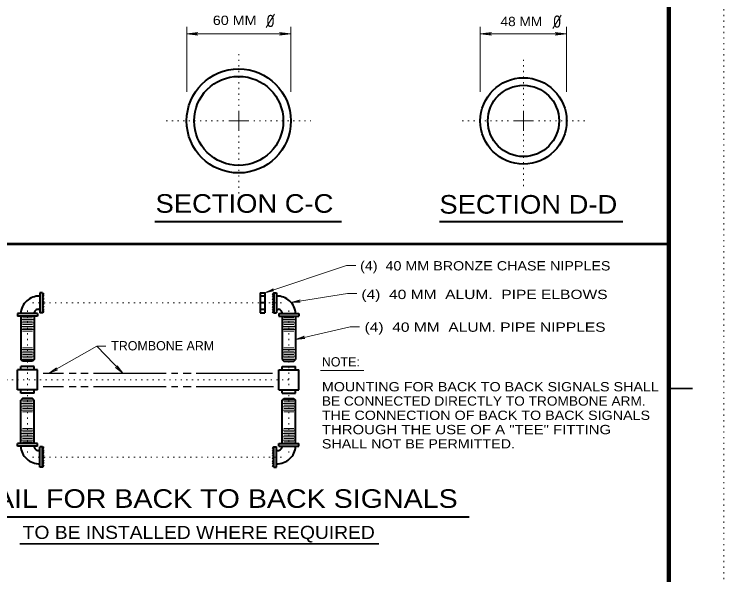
# Model space of a CAD drawing. Extents: x 312583 to 312854, y 144419 to 144597.
# Drawn here: x 312795.5 to 312853.5, y 144488.4 to 144534.2 of the extents above; entities that cross this region are included whole.
import ezdxf
from ezdxf.enums import TextEntityAlignment as Align

# ---------------------------------------------------------------- set-up
doc = ezdxf.new("R2010")
doc.units = 0
doc.header["$LTSCALE"] = 0.3
doc.linetypes.add('DOTTED', pattern=[1.5, 0.3, -1.2])
for name, color, linetype, lineweight in [('1', 7, 'Continuous', 35), ('2', 7, 'Continuous', 13), ('62', 7, 'DOTTED', 13)]:
    doc.layers.add(name, color=color, linetype=linetype, lineweight=lineweight)

msp = doc.modelspace()

# ---------------------------------------------------------------- linework, layer by layer
at = {"layer": '1', "lineweight": 158}
msp.add_line((312849, 144423.1446), (312849, 144585.0846), dxfattribs=at)
at = {"layer": '1', "lineweight": 53}
msp.add_line((312849, 144515.4129), (312762.6698, 144515.4129), dxfattribs=at)
at = {"layer": '1', "lineweight": 40}
for p, q in [((312797.6188, 144511.4311), (312797.6188, 144509.7904)), ((312797.8335, 144511.4311), (312797.6188, 144511.4311)), ((312797.8335, 144511.4311), (312797.8335, 144509.7904)), ((312797.8335, 144511.4311), (312797.9408, 144511.3314)), ((312815.6048, 144511.4311), (312815.9882, 144511.4311)), ((312815.6048, 144511.4311), (312815.6048, 144509.7904)), ((312815.9882, 144511.4311), (312815.9882, 144509.7904)), ((312816.7242, 144511.4311), (312816.6245, 144511.3314)), ((312816.7242, 144511.4311), (312816.7242, 144509.7904)), ((312816.7242, 144511.4311), (312816.9465, 144511.4311)), ((312816.9465, 144511.4311), (312816.9465, 144509.7904)), ((312797.8335, 144511.2241), (312797.9408, 144511.3314)), ((312797.8335, 144511.2241), (312797.9408, 144511.1244)), ((312797.8335, 144511.0171), (312797.9408, 144511.1244)), ((312797.8335, 144511.0171), (312797.9408, 144510.9174)), ((312797.8335, 144510.8101), (312797.9408, 144510.9174)), ((312797.8335, 144510.8101), (312797.9408, 144510.7028)), ((312815.9882, 144511.1628), (312815.6048, 144511.1628)), ((312816.7242, 144511.2241), (312816.6245, 144511.3314)), ((312816.7242, 144511.2241), (312816.6245, 144511.1244)), ((312816.7242, 144511.0171), (312816.6245, 144511.1244)), ((312816.7242, 144511.0171), (312816.6245, 144510.9174)), ((312816.7242, 144510.8101), (312816.6245, 144510.9174)), ((312816.7242, 144510.8101), (312816.6245, 144510.7028)), ((312797.8335, 144510.6031), (312797.9408, 144510.7028)), ((312797.8335, 144510.6031), (312797.9408, 144510.4958)), ((312797.8335, 144510.3961), (312797.9408, 144510.4958)), ((312797.8335, 144510.3961), (312797.9408, 144510.2888)), ((312797.8335, 144510.1891), (312797.9408, 144510.2888)), ((312815.9882, 144510.6108), (312815.6048, 144510.6108)), ((312816.7242, 144510.6031), (312816.6245, 144510.7028)), ((312816.7242, 144510.6031), (312816.6245, 144510.4958)), ((312816.7242, 144510.3961), (312816.6245, 144510.4958)), ((312816.7242, 144510.3961), (312816.6245, 144510.2888)), ((312816.7242, 144510.1891), (312816.6245, 144510.2888)), ((312795.7788, 144509.7368), (312795.7788, 144509.5144)), ((312797.4272, 144509.7368), (312795.7788, 144509.7368)), ((312797.4272, 144509.7368), (312797.4272, 144509.5144)), ((312797.6188, 144510.0818), (312797.5115, 144510.0818)), ((312797.8335, 144509.7904), (312797.6188, 144509.7904)), ((312797.8335, 144510.1891), (312797.9408, 144510.0818)), ((312797.8335, 144509.9744), (312797.9408, 144510.0818)), ((312797.8335, 144509.9744), (312797.9408, 144509.8748)), ((312797.8335, 144509.7904), (312797.9408, 144509.8748)), ((312815.9882, 144510.0818), (312815.6048, 144510.0818)), ((312815.6048, 144509.7904), (312815.9882, 144509.7904)), ((312816.7242, 144510.1891), (312816.6245, 144510.0818)), ((312816.7242, 144509.9744), (312816.6245, 144510.0818)), ((312816.7242, 144509.9744), (312816.6245, 144509.8748)), ((312816.7242, 144509.7904), (312816.6245, 144509.8748)), ((312816.7242, 144509.7904), (312816.9465, 144509.7904)), ((312816.9465, 144510.0818), (312817.0462, 144510.0818)), ((312817.1382, 144509.7368), (312817.1382, 144509.5144)), ((312817.1382, 144509.7368), (312818.7788, 144509.7368)), ((312818.7788, 144509.7368), (312818.7788, 144509.5144)), ((312797.4272, 144509.5144), (312795.7788, 144509.5144)), ((312796.0548, 144509.5144), (312796.0548, 144505.9724)), ((312797.1512, 144509.5144), (312797.1512, 144505.9724)), ((312817.1382, 144509.5144), (312818.7788, 144509.5144)), ((312817.4142, 144509.5144), (312817.4142, 144505.9724)), ((312818.5105, 144509.5144), (312818.5105, 144505.9724)), ((312796.1928, 144505.8344), (312796.0548, 144505.9724)), ((312797.0132, 144505.8344), (312796.1928, 144505.8344)), ((312797.1512, 144505.9724), (312797.0132, 144505.8344)), ((312817.4142, 144505.9724), (312817.5522, 144505.8344)), ((312817.5522, 144505.8344), (312818.3725, 144505.8344)), ((312818.3725, 144505.8344), (312818.5105, 144505.9724)), ((312795.7788, 144503.4961), (312795.7788, 144505.1368)), ((312797.4272, 144505.1368), (312795.7788, 144505.1368)), ((312797.1512, 144505.4128), (312796.0548, 144505.4128)), ((312796.0548, 144505.1368), (312796.0548, 144505.4128)), ((312797.1512, 144505.1368), (312797.1512, 144505.4128)), ((312797.4272, 144503.4961), (312797.4272, 144505.1368)), ((312817.1382, 144503.4961), (312817.1382, 144505.1368)), ((312817.1382, 144505.1368), (312818.7788, 144505.1368)), ((312817.4142, 144505.4128), (312818.5105, 144505.4128)), ((312817.4142, 144505.1368), (312817.4142, 144505.4128)), ((312818.5105, 144505.1368), (312818.5105, 144505.4128)), ((312818.7788, 144503.4961), (312818.7788, 144505.1368)), ((312797.4272, 144503.4961), (312795.7788, 144503.4961)), ((312796.0548, 144503.2201), (312796.0548, 144503.4961)), ((312797.1512, 144503.2201), (312797.1512, 144503.4961)), ((312817.1382, 144503.4961), (312818.7788, 144503.4961)), ((312817.4142, 144503.2201), (312817.4142, 144503.4961)), ((312818.5105, 144503.2201), (312818.5105, 144503.4961)), ((312797.1512, 144503.2201), (312796.0548, 144503.2201)), ((312796.1928, 144502.7908), (312796.0548, 144502.6604)), ((312797.0132, 144502.7908), (312796.1928, 144502.7908)), ((312797.1512, 144502.6604), (312797.0132, 144502.7908)), ((312817.4142, 144503.2201), (312818.5105, 144503.2201)), ((312817.4142, 144502.6604), (312817.5522, 144502.7908)), ((312817.5522, 144502.7908), (312818.3725, 144502.7908)), ((312818.3725, 144502.7908), (312818.5105, 144502.6604)), ((312796.0548, 144499.1108), (312796.0548, 144502.6604)), ((312797.1512, 144499.1108), (312797.1512, 144502.6604)), ((312817.4142, 144499.1108), (312817.4142, 144502.6604)), ((312818.5105, 144499.1108), (312818.5105, 144502.6604)), ((312795.7788, 144498.8961), (312795.7788, 144499.1108)), ((312797.4272, 144499.1108), (312795.7788, 144499.1108)), ((312797.4272, 144498.8961), (312795.7788, 144498.8961)), ((312797.4272, 144498.8961), (312797.4272, 144499.1108)), ((312797.6188, 144497.1941), (312797.6188, 144498.8424)), ((312797.8335, 144498.8424), (312797.6188, 144498.8424)), ((312797.8335, 144497.1941), (312797.8335, 144498.8424)), ((312797.8335, 144498.8424), (312797.9408, 144498.7581)), ((312797.8335, 144498.6508), (312797.9408, 144498.7581)), ((312797.8335, 144498.6508), (312797.9408, 144498.5511)), ((312816.7242, 144498.8424), (312816.6245, 144498.7581)), ((312816.7242, 144498.6508), (312816.6245, 144498.7581)), ((312816.7242, 144498.6508), (312816.6245, 144498.5511)), ((312816.7242, 144497.1941), (312816.7242, 144498.8424)), ((312816.7242, 144498.8424), (312816.9465, 144498.8424)), ((312816.9465, 144497.1941), (312816.9465, 144498.8424)), ((312817.1382, 144498.8961), (312817.1382, 144499.1108)), ((312817.1382, 144499.1108), (312818.7788, 144499.1108)), ((312817.1382, 144498.8961), (312818.7788, 144498.8961)), ((312818.7788, 144498.8961), (312818.7788, 144499.1108)), ((312797.6188, 144498.5434), (312797.5115, 144498.5434)), ((312797.8335, 144498.4438), (312797.9408, 144498.5511)), ((312797.8335, 144498.4438), (312797.9408, 144498.3441)), ((312797.8335, 144498.2368), (312797.9408, 144498.3441)), ((312797.8335, 144498.2368), (312797.9408, 144498.1294)), ((312797.8335, 144498.0298), (312797.9408, 144498.1294)), ((312816.7242, 144498.4438), (312816.6245, 144498.5511)), ((312816.7242, 144498.4438), (312816.6245, 144498.3441)), ((312816.7242, 144498.2368), (312816.6245, 144498.3441)), ((312816.7242, 144498.2368), (312816.6245, 144498.1294)), ((312816.7242, 144498.0298), (312816.6245, 144498.1294)), ((312816.9465, 144498.5434), (312817.0462, 144498.5434)), ((312797.8335, 144498.0298), (312797.9408, 144497.9224)), ((312797.8335, 144497.8228), (312797.9408, 144497.9224)), ((312797.8335, 144497.8228), (312797.9408, 144497.7154)), ((312797.8335, 144497.6158), (312797.9408, 144497.7154)), ((312797.8335, 144497.6158), (312797.9408, 144497.5084)), ((312797.8335, 144497.4011), (312797.9408, 144497.5084)), ((312816.7242, 144498.0298), (312816.6245, 144497.9224)), ((312816.7242, 144497.8228), (312816.6245, 144497.9224)), ((312816.7242, 144497.8228), (312816.6245, 144497.7154)), ((312816.7242, 144497.6158), (312816.6245, 144497.7154)), ((312816.7242, 144497.6158), (312816.6245, 144497.5084)), ((312816.7242, 144497.4011), (312816.6245, 144497.5084)), ((312797.8335, 144497.1941), (312797.6188, 144497.1941)), ((312797.8335, 144497.4011), (312797.9408, 144497.3014)), ((312797.8335, 144497.1941), (312797.9408, 144497.3014)), ((312816.7242, 144497.4011), (312816.6245, 144497.3014)), ((312816.7242, 144497.1941), (312816.6245, 144497.3014)), ((312816.7242, 144497.1941), (312816.9465, 144497.1941))]:
    msp.add_line(p, q, dxfattribs=at)
at = {"layer": '1', "linetype": 'DOTTED', "lineweight": 13}
for p, q in [((312796.5992, 144498.3748), (312796.5992, 144510.2811)), ((312797.0132, 144510.6108), (312817.6365, 144510.6108)), ((312817.9585, 144498.3748), (312817.9585, 144510.2811)), ((312792.5588, 144504.3164), (312818.2038, 144504.3164)), ((312797.0132, 144498.0144), (312817.6365, 144498.0144))]:
    msp.add_line(p, q, dxfattribs=at)
at = {"layer": '1', "lineweight": 13}
for p, q in [((312797.1512, 144509.2461), (312796.0548, 144509.2461)), ((312797.0132, 144509.3841), (312796.1928, 144509.3841)), ((312797.0132, 144509.1081), (312796.1928, 144509.1081)), ((312817.4142, 144509.2461), (312818.5105, 144509.2461)), ((312817.5522, 144509.3841), (312818.3725, 144509.3841)), ((312817.5522, 144509.1081), (312818.3725, 144509.1081)), ((312797.1512, 144508.9701), (312796.0548, 144508.9701)), ((312797.1512, 144508.6941), (312796.0548, 144508.6941)), ((312797.0132, 144508.8321), (312796.1928, 144508.8321)), ((312797.0132, 144508.5561), (312796.1928, 144508.5561)), ((312817.4142, 144508.9701), (312818.5105, 144508.9701)), ((312817.4142, 144508.6941), (312818.5105, 144508.6941)), ((312817.5522, 144508.8321), (312818.3725, 144508.8321)), ((312817.5522, 144508.5561), (312818.3725, 144508.5561)), ((312797.1512, 144508.4258), (312796.0548, 144508.4258)), ((312797.0132, 144508.2878), (312796.1928, 144508.2878)), ((312817.4142, 144508.4258), (312818.5105, 144508.4258)), ((312817.5522, 144508.2878), (312818.3725, 144508.2878)), ((312797.1512, 144506.7928), (312796.0548, 144506.7928)), ((312797.0132, 144506.9308), (312796.1928, 144506.9308)), ((312817.4142, 144506.7928), (312818.5105, 144506.7928)), ((312817.5522, 144506.9308), (312818.3725, 144506.9308)), ((312797.1512, 144506.5244), (312796.0548, 144506.5244)), ((312797.1512, 144506.2484), (312796.0548, 144506.2484)), ((312797.0132, 144506.6548), (312796.1928, 144506.6548)), ((312797.0132, 144506.3864), (312796.1928, 144506.3864)), ((312817.4142, 144506.5244), (312818.5105, 144506.5244)), ((312817.4142, 144506.2484), (312818.5105, 144506.2484)), ((312817.5522, 144506.6548), (312818.3725, 144506.6548)), ((312817.5522, 144506.3864), (312818.3725, 144506.3864)), ((312797.1512, 144505.9724), (312796.0548, 144505.9724)), ((312797.0132, 144506.1104), (312796.1928, 144506.1104)), ((312817.4142, 144505.9724), (312818.5105, 144505.9724)), ((312817.5522, 144506.1104), (312818.3725, 144506.1104)), ((312797.1512, 144502.6604), (312796.0548, 144502.6604)), ((312797.1512, 144502.3844), (312796.0548, 144502.3844)), ((312797.1512, 144502.1084), (312796.0548, 144502.1084)), ((312797.0132, 144502.5224), (312796.1928, 144502.5224)), ((312797.0132, 144502.2464), (312796.1928, 144502.2464)), ((312817.4142, 144502.6604), (312818.5105, 144502.6604)), ((312817.4142, 144502.3844), (312818.5105, 144502.3844)), ((312817.4142, 144502.1084), (312818.5105, 144502.1084)), ((312817.5522, 144502.5224), (312818.3725, 144502.5224)), ((312817.5522, 144502.2464), (312818.3725, 144502.2464)), ((312797.1512, 144501.8324), (312796.0548, 144501.8324)), ((312797.0132, 144501.9704), (312796.1928, 144501.9704)), ((312797.0132, 144501.7021), (312796.1928, 144501.7021)), ((312817.4142, 144501.8324), (312818.5105, 144501.8324)), ((312817.5522, 144501.9704), (312818.3725, 144501.9704)), ((312817.5522, 144501.7021), (312818.3725, 144501.7021)), ((312797.1512, 144500.2071), (312796.0548, 144500.2071)), ((312797.1512, 144499.9311), (312796.0548, 144499.9311)), ((312797.0132, 144500.3451), (312796.1928, 144500.3451)), ((312797.0132, 144500.0691), (312796.1928, 144500.0691)), ((312797.0132, 144499.8008), (312796.1928, 144499.8008)), ((312817.4142, 144500.2071), (312818.5105, 144500.2071)), ((312817.4142, 144499.9311), (312818.5105, 144499.9311)), ((312817.5522, 144500.3451), (312818.3725, 144500.3451)), ((312817.5522, 144500.0691), (312818.3725, 144500.0691)), ((312817.5522, 144499.8008), (312818.3725, 144499.8008)), ((312797.1512, 144499.6628), (312796.0548, 144499.6628)), ((312797.1512, 144499.3868), (312796.0548, 144499.3868)), ((312797.0132, 144499.5248), (312796.1928, 144499.5248)), ((312797.0132, 144499.2488), (312796.1928, 144499.2488)), ((312817.4142, 144499.6628), (312818.5105, 144499.6628)), ((312817.4142, 144499.3868), (312818.5105, 144499.3868)), ((312817.5522, 144499.5248), (312818.3725, 144499.5248)), ((312817.5522, 144499.2488), (312818.3725, 144499.2488))]:
    msp.add_line(p, q, dxfattribs=at)
at = {"layer": '1', "lineweight": 25}
for p, q in [((312797.8718, 144504.8608), (312799.5508, 144504.8608)), ((312800.0185, 144504.8608), (312800.5782, 144504.8608)), ((312800.9538, 144504.8608), (312801.5672, 144504.8608)), ((312801.9888, 144504.8608), (312807.9458, 144504.8608)), ((312808.3675, 144504.8608), (312808.8812, 144504.8608)), ((312809.3105, 144504.8608), (312809.9622, 144504.8608)), ((312810.3838, 144504.8608), (312816.6245, 144504.8608)), ((312797.8718, 144503.7644), (312799.5508, 144503.7644)), ((312800.0185, 144503.7644), (312800.5782, 144503.7644)), ((312800.9538, 144503.7644), (312801.5672, 144503.7644)), ((312801.9888, 144503.7644), (312807.9458, 144503.7644)), ((312808.3675, 144503.7644), (312808.8812, 144503.7644)), ((312809.3105, 144503.7644), (312809.9622, 144503.7644)), ((312810.3838, 144503.7644), (312816.7012, 144503.7644))]:
    msp.add_line(p, q, dxfattribs=at)
at = {"layer": '1'}
msp.add_line((312849, 144503.6216), (312850.932, 144503.6216), dxfattribs=at)
at = {"layer": '1', "lineweight": 40}
for centre, radius in [((312813.8612, 144525.4808), 4.255), ((312813.8612, 144525.4808), 3.6417), ((312837.1297, 144525.4808), 3.5267), ((312837.1297, 144525.4808), 2.9133)]:
    msp.add_circle(centre, radius, dxfattribs=at)
for centre, radius, start, end in [((312797.5389, 144509.6778), 1.4853, 87.04189, 177.70529), ((312817.0231, 144509.6778), 1.4853, 2.29471, 92.95811), ((312797.5049, 144509.7299), 0.3549, 88.7647, 178.79588), ((312817.0571, 144509.7299), 0.3549, 1.20412, 91.2353), ((312797.5389, 144498.9539), 1.4853, 182.29471, 272.95811), ((312797.5049, 144498.9019), 0.3549, 181.20412, 271.2353), ((312817.0231, 144498.9539), 1.4853, 267.04189, 357.70529), ((312817.0571, 144498.9019), 0.3549, 268.7647, 358.79588)]:
    msp.add_arc(centre, radius, start, end, dxfattribs=at)
at = {"layer": '2'}
for p, q in [((312816.1029, 144533.1076), (312816.7776, 144534.1963)), ((312839.5309, 144533.0463), (312840.2056, 144534.1349)), ((312809.6093, 144527.8636), (312809.6093, 144533.1843)), ((312818.1193, 144527.8636), (312818.1193, 144533.1843)), ((312833.6046, 144527.8636), (312833.6046, 144533.1843)), ((312840.6579, 144527.8636), (312840.6579, 144533.1843)), ((312809.6093, 144532.6016), (312810.5293, 144532.7166)), ((312809.6093, 144532.6016), (312818.1193, 144532.6016)), ((312809.6093, 144532.6016), (312810.5293, 144532.4866)), ((312810.5293, 144532.7166), (312810.2379, 144532.6016)), ((312810.5293, 144532.4866), (312810.2379, 144532.6016)), ((312817.1916, 144532.7166), (312817.4906, 144532.6016)), ((312818.1193, 144532.6016), (312817.1916, 144532.7166)), ((312817.1916, 144532.4866), (312817.4906, 144532.6016)), ((312818.1193, 144532.6016), (312817.1916, 144532.4866)), ((312833.6046, 144532.6016), (312834.5246, 144532.7166)), ((312833.6046, 144532.6016), (312840.6579, 144532.6016)), ((312833.6046, 144532.6016), (312834.5246, 144532.4866)), ((312834.5246, 144532.7166), (312834.2332, 144532.6016)), ((312834.5246, 144532.4866), (312834.2332, 144532.6016)), ((312839.7302, 144532.7166), (312840.0292, 144532.6016)), ((312840.6579, 144532.6016), (312839.7302, 144532.7166)), ((312839.7302, 144532.4866), (312840.0292, 144532.6016)), ((312840.6579, 144532.6016), (312839.7302, 144532.4866)), ((312813.8643, 144525.4793), (312813.8643, 144526.2996)), ((312837.1312, 144525.4793), (312837.1312, 144526.2996)), ((312813.8643, 144525.4793), (312813.0439, 144525.4793)), ((312813.8643, 144525.4793), (312814.6769, 144525.4793)), ((312813.8643, 144525.4793), (312813.8643, 144524.6589)), ((312837.1312, 144525.4793), (312836.3109, 144525.4793)), ((312837.1312, 144525.4793), (312837.9516, 144525.4793)), ((312837.1312, 144525.4793), (312837.1312, 144524.6589)), ((312815.9882, 144511.4311), (312822.6812, 144513.6621)), ((312822.6812, 144513.6621), (312823.4248, 144513.6621)), ((312815.9882, 144511.4311), (312816.6628, 144511.7531)), ((312815.9882, 144511.4311), (312816.7165, 144511.5844)), ((312816.6628, 144511.7531), (312816.4635, 144511.5921)), ((312816.7165, 144511.5844), (312816.4635, 144511.5921)), ((312818.1502, 144510.6491), (312822.7502, 144511.3774)), ((312818.1502, 144510.6491), (312818.8708, 144510.8561)), ((312818.8708, 144510.8561), (312818.6485, 144510.7258)), ((312822.7502, 144511.3774), (312823.5015, 144511.3774)), ((312818.1502, 144510.6491), (312818.8938, 144510.6721)), ((312818.8938, 144510.6721), (312818.6485, 144510.7258)), ((312818.5105, 144507.6208), (312822.9725, 144508.6634)), ((312822.9725, 144508.6634), (312823.7238, 144508.6634)), ((312818.5105, 144507.6208), (312819.2082, 144507.8814)), ((312818.5105, 144507.6208), (312819.2542, 144507.7051)), ((312819.2082, 144507.8814), (312819.0012, 144507.7358)), ((312819.2542, 144507.7051), (312819.0012, 144507.7358)), ((312802.2648, 144507.0841), (312803.0085, 144507.0841)), ((312798.3778, 144504.8608), (312798.9758, 144505.3131)), ((312798.3778, 144504.8608), (312799.0678, 144505.1521)), ((312798.9758, 144505.3131), (312798.8148, 144505.1138)), ((312799.0678, 144505.1521), (312798.8148, 144505.1138)), ((312803.8058, 144505.3361), (312804.0358, 144505.2288)), ((312804.3808, 144504.8608), (312803.8058, 144505.3361)), ((312803.9362, 144505.4664), (312804.0358, 144505.2288)), ((312804.3808, 144504.8608), (312803.9362, 144505.4664)), ((312820.5539, 144505.0908), (312824.0729, 144505.0908))]:
    msp.add_line(p, q, dxfattribs=at)
at = {"layer": '2', "linetype": 'DOTTED'}
for p, q in [((312813.8643, 144526.7059), (312813.8643, 144531.2293)), ((312837.1312, 144526.7059), (312837.1312, 144530.7846)), ((312812.6376, 144525.4793), (312807.8076, 144525.4793)), ((312815.0909, 144525.4793), (312819.7523, 144525.4793)), ((312835.9046, 144525.4793), (312831.8412, 144525.4793)), ((312838.3579, 144525.4793), (312842.4749, 144525.4793)), ((312813.8643, 144524.2526), (312813.8643, 144519.5529)), ((312837.1312, 144524.3983), (312837.1312, 144520.1586))]:
    msp.add_line(p, q, dxfattribs=at)
at = {"layer": '2', "lineweight": 40}
for p, q in [((312807.0026, 144517.2529), (312822.2505, 144517.2529)), ((312830.2696, 144517.2529), (312845.2503, 144517.2529)), ((312789.1347, 144493.1384), (312832.6981, 144493.1384))]:
    msp.add_line(p, q, dxfattribs=at)
at = {"layer": '2', "lineweight": 35}
msp.add_line((312795.9764, 144490.9326), (312825.3173, 144490.9326), dxfattribs=at)
at = {"layer": '2'}
msp.add_lwpolyline([(312798.3778, 144504.8608), (312802.2648, 144507.0841), (312804.3808, 144504.8608)], dxfattribs=at)
at = {"layer": '62'}
msp.add_lwpolyline([(312601.2, 144418.5846), (312853.5, 144418.5846), (312853.5, 144596.7846)], dxfattribs=at)

# ---------------------------------------------------------------- texts
at = {"layer": '2'}
for s, height, width, p in [('60 MM', 0.76, 1.15, (312811.7472, 144533.3255)), ('48 MM', 0.76, 1.1, (312835.2507, 144533.2287)), ('SECTION C-C', 1.52, 1.1, (312807.0655, 144517.9748)), ('SECTION D-D', 1.52, 1.1, (312830.2609, 144517.9031)), ('(4)  40 MM BRONZE CHASE NIPPLES', 0.76, 1.15, (312823.7799, 144513.2614)), ('(4)  40 MM  ALUM.  PIPE ELBOWS', 0.76, 1.25, (312823.8848, 144510.9229)), ('(4)  40 MM  ALUM. PIPE NIPPLES', 0.76, 1.25, (312824.1455, 144508.2499)), ('MOUNTING FOR BACK TO BACK SIGNALS SHALL', 0.76, 1.15, (312820.6559, 144503.3782)), ('BE CONNECTED DIRECTLY TO TROMBONE ARM.', 0.76, 1.1, (312820.6559, 144502.2119)), ('THE CONNECTION OF BACK TO BACK SIGNALS', 0.76, 1.15, (312820.6559, 144501.0456)), ('THROUGH THE USE OF A "TEE" FITTING', 0.76, 1.2, (312820.6559, 144499.8793)), ('SHALL NOT BE PERMITTED.', 0.76, 1.15, (312820.6559, 144498.713)), ('DETAIL FOR BACK TO BACK SIGNALS', 1.52, 1.15, (312789.2802, 144493.8582))]:
    msp.add_text(s, height=height, dxfattribs=dict(at, width=width)).set_placement(p)
for s, height, width, p in [('0', 0.9813, 0.85, (312816.4595, 144533.1613)), ('0', 0.9813, 0.85, (312839.8798, 144533.1076)), ('TO BE INSTALLED WHERE REQUIRED', 1.07, 1.1, (312810.596, 144491.3192))]:
    msp.add_text(s, height=height, dxfattribs=dict(at, width=width)).set_placement(p, align=Align.CENTER)
for s, p in [('TROMBONE ARM', (312803.4428, 144506.7269)), ('NOTE:', (312820.6535, 144505.4135))]:
    msp.add_text(s, height=0.76, dxfattribs=at).set_placement(p)

doc.saveas('drawing.dxf')
